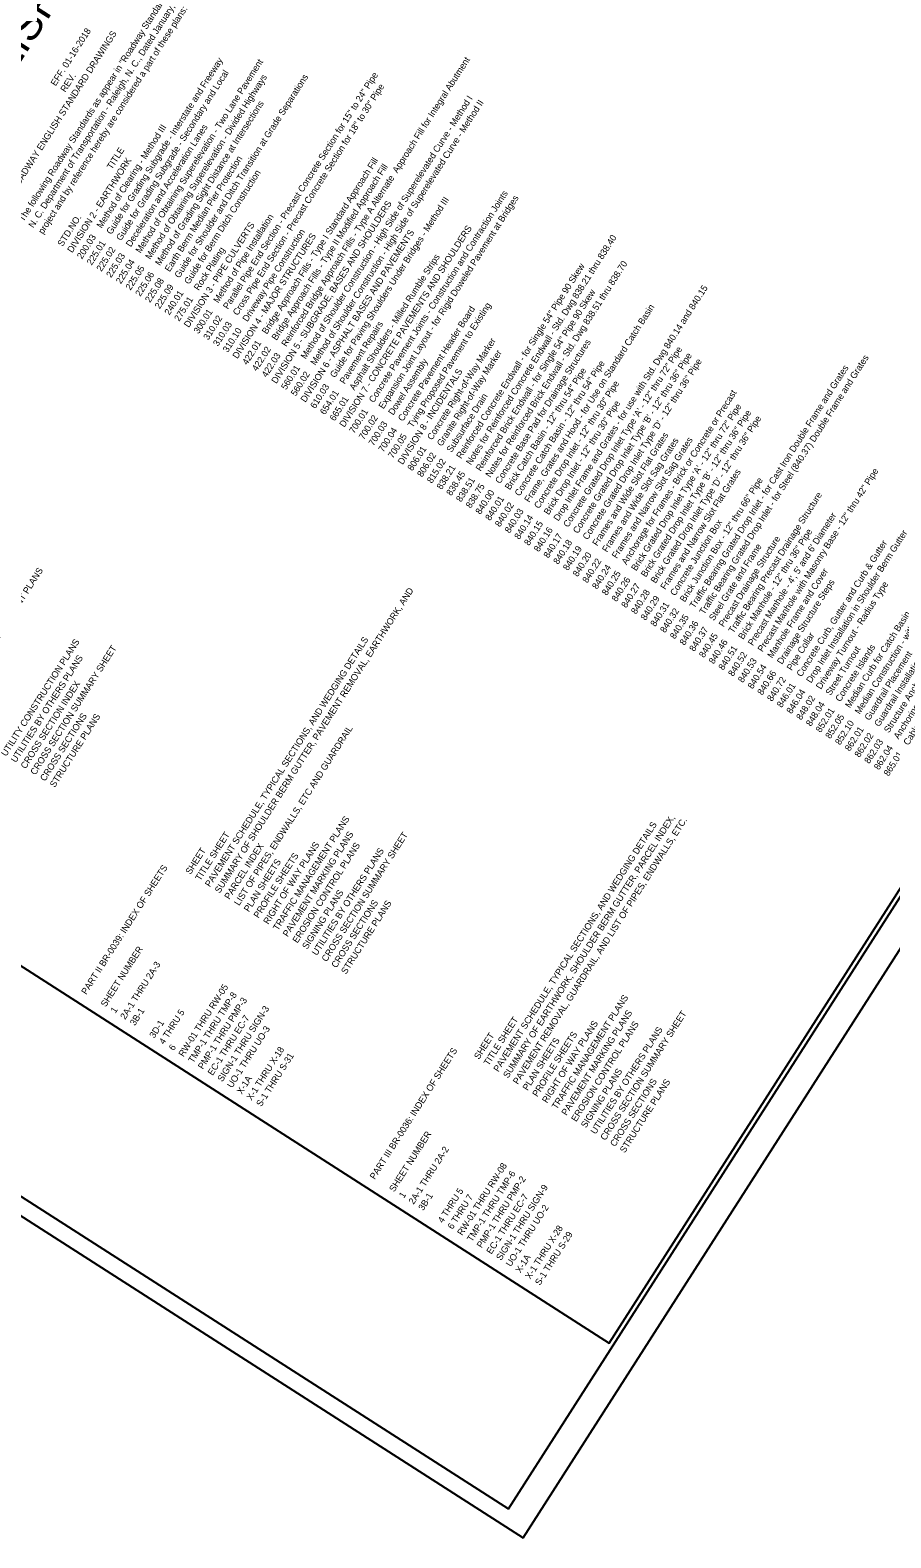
# Model space of a CAD drawing. Extents: x 2347249 to 2361994, y 830101 to 846299.
# Drawn here: x 2351497 to 2357017, y 830101 to 839761 of the extents above; entities that cross this region are included whole.
import ezdxf

# ---------------------------------------------------------------- set-up
doc = ezdxf.new("R2010")
doc.units = 0
for name, color, linetype in [('Sheet Data Field CELL', 7, 'Continuous'), ('Sheet Plot Border Inside CELL', 7, 'Continuous'), ('Sheet Plot Border Outside CELL', 7, 'Continuous'), ('Sheet Symbology CELL', 7, 'Continuous')]:
    doc.layers.add(name, color=color, linetype=linetype)

msp = doc.modelspace()

# ---------------------------------------------------------------- linework, layer by layer
at = {"layer": 'Sheet Plot Border Inside CELL'}
msp.add_lwpolyline([(2354564.1, 830285.9), (2361823.6, 841618.9), (2354715.9, 846171.7), (2347456.5, 834838.7)], close=True, dxfattribs=at)
at = {"layer": 'Sheet Plot Border Outside CELL'}
msp.add_lwpolyline([(2354658.7, 830100.6), (2361994.4, 841552.6), (2354584.3, 846299.2), (2347248.6, 834847.2)], close=True, dxfattribs=at)
at = {"layer": 'Sheet Symbology CELL'}
msp.add_lwpolyline([(2354678.6, 846075.7), (2348144.5, 835875), (2355211, 831348.5), (2361745.1, 841549.2)], close=True, dxfattribs=at)

# ---------------------------------------------------------------- texts
at = {"layer": 'Sheet Data Field CELL'}
for s, height, p in [('INDEX OF SHEETS, GENERAL NOTES AND 2018 ', 200, (2350018.7, 837720)), ('ROADWAY ENGLISH STANDARD DRAWINGS', 200, (2350290, 837764.1)), ('The following Roadway Standards as appear in "Roadway Standard Drawings" Highway Design Branch -', 42, (2351455.7, 838530.2)), ('N. C. Department of Transportation - Raleigh, N. C., Dated January, 2018 are applicable to this ', 42, (2351518, 838490.3)), ('project and by reference hereby are considered a part of these plans:', 42, (2351580.3, 838450.4)), ('                                                      EFF. 01-16-2018', 42, (2351206.4, 838689.9)), ('2018 ROADWAY ENGLISH STANDARD DRAWINGS', 42, (2351331.1, 838610)), ('225.01    Guide for Grading Subgrade - Interstate and Freeway', 42, (2351891.9, 838250.8)), ('225.04    Method of Obtaining Superelevation - Two Lane Pavement', 42, (2352078.9, 838131)), ('422.03    Reinforced Bridge Approach Fills - Type A Alternate  Approach Fill for Integral Abutment', 42, (2353013.7, 837532.2)), ('                                                      REV. ', 42, (2351268.7, 838650)), ('225.02    Guide for Grading Subgrade - Secondary and Local', 42, (2351954.3, 838210.8)), ('225.05    Method of Obtaining Superelevation - Divided Highways', 42, (2352141.2, 838091.1)), ('225.09    Guide for Shoulder and Ditch Transition at Grade Separations', 42, (2352328.2, 837971.3)), ('310.02    Parallel Pipe End Section - Precast Concrete Section for 15" to 24" Pipe', 42, (2352639.8, 837771.7)), ('310.03    Cross Pipe End Section - Precast Concrete Section for 18" to 30" Pipe', 42, (2352702.1, 837731.8)), ('225.06    Method of Grading Sight Distance at Intersections', 42, (2352203.5, 838051.2)), ('560.01    Method of Shoulder Construction - High Side of Superelevated Curve - Method I', 42, (2353138.3, 837452.4)), ('560.02    Method of Shoulder Construction - High Side of Superelevated Curve - Method II', 42, (2353200.7, 837412.5)), ('200.03    Method of Clearing - Method III', 42, (2351829.6, 838290.7)), ('225.03    Deceleration and Acceleration Lanes', 42, (2352016.6, 838170.9)), ('STD.NO.                       TITLE', 42, (2351705, 838370.5)), ('DIVISION 2 - EARTHWORK', 42, (2351767.3, 838330.6)), ('225.08    Earth Berm Median Pier Protection', 42, (2352265.9, 838011.3)), ('422.01    Bridge Approach Fills - Type I Standard Approach Fill', 42, (2352889.1, 837612.1)), ('422.02    Bridge Approach Fills - Type II Modified Approach Fill', 42, (2352951.4, 837572.1)), ('240.01    Guide for Berm Ditch Construction', 42, (2352390.5, 837931.4)), ('700.01    Concrete Pavement Joints - Construction and Contraction Joints ', 42, (2353574.6, 837172.9)), ('700.02    Expansion Joint Layout - for Rigid Doweled Pavement at Bridges', 42, (2353636.9, 837133)), ('DIVISION 5 - SUBGRADE, BASES AND SHOULDERS', 42, (2353076, 837492.3)), ('610.03    Guide for Paving Shoulders Under Bridges - Method III', 42, (2353325.3, 837332.6)), ('DIVISION 3 - PIPE CULVERTS', 42, (2352515.1, 837851.6)), ('300.01    Method of Pipe Installation ', 42, (2352577.5, 837811.7)), ('DIVISION 7 - CONCRETE PAVEMENTS AND SHOULDERS', 42, (2353512.3, 837212.9)), ('310.10    Driveway Pipe Construction', 42, (2352764.4, 837691.9)), ('DIVISION 4 - MAJOR STRUCTURES', 42, (2352826.7, 837652)), ('DIVISION 6 - ASPHALT BASES AND PAVEMENTS', 42, (2353263, 837372.5)), ('838.45    Notes for Reinforced Concrete Endwall - Std. Dwg 838.21 thru 838.40', 42, (2354197.8, 836773.7)), ('275.01    Rock Plating', 42, (2352452.8, 837891.5)), ('665.01    Asphalt Shoulders - Milled Rumble Strips', 42, (2353450, 837252.8)), ('838.21    Reinforced Concrete Endwall - for Single 54" Pipe 90 Skew', 42, (2354135.5, 836813.7)), ('838.75    Notes for Reinforced Brick Endwall - Std. Dwg 838.51 thru 838.70', 42, (2354322.4, 836693.9)), ('840.16    Drop Inlet Frame and Grates - for use with Std. Dwg 840.14 and 840.15', 42, (2354758.7, 836414.5)), ('838.51    Reinforced Brick Endwall - for Single 54" Pipe 90 Skew', 42, (2354260.1, 836733.8)), ('700.04    Concrete Pavement Header Board', 42, (2353761.6, 837053.2)), ('700.05    Tying Proposed Pavement to Existing', 42, (2353823.9, 837013.3)), ('840.03    Frame, Grates and Hood - for Use on Standard Catch Basin', 42, (2354571.7, 836534.2)), ('654.01    Pavement Repairs', 42, (2353387.6, 837292.7)), ('806.01    Concrete Right-of-Way Marker', 42, (2353948.5, 836933.4)), ('840.00    Concrete Base Pad for Drainage Structures', 42, (2354384.8, 836654)), ('840.17    Concrete Grated Drop Inlet Type \'A\' - 12" thru 72" Pipe', 42, (2354821, 836374.5)), ('700.03    Dowel Assembly', 42, (2353699.2, 837093.1)), ('806.02    Granite Right-of-Way Marker', 42, (2354010.8, 836893.5)), ('840.02    Concrete Catch Basin - 12" thru 54" Pipe', 42, (2354509.4, 836574.1)), ('840.18    Concrete Grated Drop Inlet Type \'B\' - 12" thru 36" Pipe', 42, (2354883.3, 836334.6)), ('840.19    Concrete Grated Drop Inlet Type \'D\' - 12" thru 36" Pipe', 42, (2354945.6, 836294.7)), ('840.36    Traffic Bearing Grated Drop Inlet - for Steel (840.37) Double Frame and Grates', 42, (2355693.5, 835815.7)), ('DIVISION 8 - INCIDENTALS', 42, (2353886.2, 836973.3)), ('840.01    Brick Catch Basin - 12" thru 54" Pipe', 42, (2354447.1, 836614.1)), ('840.35    Traffic Bearing Grated Drop Inlet - for Cast Iron Double Frame and Grates', 42, (2355631.2, 835855.6)), ('840.14    Concrete Drop Inlet - 12" thru 30" Pipe', 42, (2354634, 836494.3)), ('840.25    Anchorage for Frames - Brick or Concrete or Precast', 42, (2355194.9, 836135)), ('815.02    Subsurface Drain', 42, (2354073.2, 836853.6)), ('840.15    Brick Drop Inlet - 12" thru 30" Pipe', 42, (2354696.4, 836454.4)), ('840.26    Brick Grated Drop Inlet Type \'A\' - 12" thru 72" Pipe', 42, (2355257.2, 836095.1)), ('840.27    Brick Grated Drop Inlet Type \'B\' - 12" thru 36" Pipe', 42, (2355319.6, 836055.2)), ('840.28    Brick Grated Drop Inlet Type \'D\' - 12" thru 36" Pipe', 42, (2355381.9, 836015.3)), ('840.20    Frames and Wide Slot Flat Grates', 42, (2355008, 836254.8)), ('840.22    Frames and Wide Slot Sag Grates', 42, (2355070.3, 836214.9)), ('840.24    Frames and Narrow Slot Sag Grates', 42, (2355132.6, 836174.9)), ('840.29    Frames and Narrow Slot Flat Grates', 42, (2355444.2, 835975.3)), ('840.32    Brick Junction Box - 12" thru 66" Pipe', 42, (2355568.8, 835895.5)), ('840.53    Precast Manhole with Masonry Base - 12" thru 42" Pipe', 42, (2356067.4, 835576.1)), ('840.46    Traffic Bearing Precast Drainage Structure', 42, (2355880.4, 835695.9)), ('852.05    Median Curb for Catch Basin - for Use with 1\'-6" Curb and Gutter', 42, (2356628.3, 835216.9)), ("840.52    Precast Manhole - 4', 5' and 6' Diameter", 42, (2356005.1, 835616.1)), ('840.31    Concrete Junction Box', 42, (2355506.5, 835935.4)), ('840.45    Precast Drainage Structure', 42, (2355818.1, 835735.8)), ('840.51    Brick Manhole - 12" thru 36" Pipe', 42, (2355942.8, 835656)), ('846.01    Concrete Curb, Gutter and Curb & Gutter', 42, (2356316.7, 835416.5)), ('846.04    Drop Inlet Installation in Shoulder Berm Gutter', 42, (2356379, 835376.6)), ('840.37    Steel Grate and Frame', 42, (2355755.8, 835775.7)), ('862.04    Anchoring End of Guardrail - B-77 and B-83 Anchor Units', 42, (2356939.9, 835017.3)), ('TRANSPORTATION MANAGEMENT PLANS', 42, (2350969.8, 835343.8)), ('840.54    Manhole Frame and Cover', 42, (2356129.7, 835536.2)), ('852.10    Median Construction - with Curb and Gutter', 42, (2356690.6, 835177)), ('SUMMARY OF SHOULDER BERM GUTTER, PAVEMENT REMOVAL, EARTHWORK, AND ', 42, (2352712.8, 834227.3)), ('840.66    Drainage Structure Steps', 42, (2356192, 835496.3)), ('848.02    Driveway Turnout - Radius Type', 42, (2356441.3, 835336.6)), ('840.72    Pipe Collar', 42, (2356254.4, 835456.4)), ('UTILITY CONSTRUCTION PLANS', 42, (2351343.7, 835104.3)), ('CROSS SECTION SUMMARY SHEET', 42, (2351530.7, 834984.5)), ('PAVEMENT SCHEDULE, TYPICAL SECTIONS, AND WEDGING DETAILS', 42, (2352650.5, 834267.2)), ('848.04    Street Turnout', 42, (2356503.6, 835296.7)), ('852.01    Concrete Islands', 42, (2356566, 835256.8)), ('UTILITIES BY OTHERS PLANS', 42, (2351406.1, 835064.4)), ('862.01    Guardrail Placement', 42, (2356752.9, 835137)), ('862.02    Guardrail Installation', 42, (2356815.2, 835097.1)), ('862.03    Structure Anchor Units', 42, (2356877.6, 835057.2)), ('CROSS SECTION INDEX', 42, (2351468.4, 835024.4)), ('865.01    Cable Guiderail', 42, (2357002.2, 834977.4)), ('CROSS SECTIONS', 42, (2351593, 834944.6)), ('STRUCTURE PLANS ', 42, (2351655.4, 834904.7)), ('LIST OF PIPES, ENDWALLS, ETC AND GUARDRAIL', 42, (2352837.5, 834147.5)), ('TRAFFIC MANAGEMENT PLANS', 42, (2353086.7, 833987.8)), ('PAVEMENT SCHEDULE, TYPICAL SECTIONS, AND WEDGING DETAILS', 42, (2354500.1, 833082.4)), ('SUMMARY OF EARTHWORK, SHOULDER BERM GUTTER, PARCEL INDEX, ', 42, (2354562.4, 833042.5)), ('PAVEMENT REMOVAL, GUARDRAIL, AND LIST OF PIPES, ENDWALLS, ETC.', 42, (2354624.8, 833002.6)), ('TITLE SHEET', 42, (2352588.2, 834307.1)), ('PARCEL INDEX', 42, (2352775.1, 834187.4)), ('RIGHT OF WAY PLANS', 42, (2353024.4, 834027.7)), ('PAVEMENT MARKING PLANS', 42, (2353149.1, 833947.9)), ('EROSION CONTROL PLANS', 42, (2353211.4, 833907.9)), ('CROSS SECTION SUMMARY SHEET', 42, (2353398.3, 833788.2)), ('SHEET', 42, (2352525.9, 834347.1)), ('PLAN SHEETS', 42, (2352899.8, 834107.5)), ('PROFILE SHEETS', 42, (2352962.1, 834067.6)), ('UTILITIES BY OTHERS PLANS', 42, (2353336, 833828.1)), ('PART II BR-0039: INDEX OF SHEETS', 42, (2351857.5, 833578.1)), ('SIGNING PLANS', 42, (2353273.7, 833868)), ('CROSS SECTIONS', 42, (2353460.7, 833748.3)), ('STRUCTURE PLANS ', 42, (2353523, 833708.4)), ('SHEET NUMBER', 42, (2351982.2, 833498.3)), ('2A-1 THRU 2A-3', 42, (2352106.8, 833418.4)), ('RW-01 THRU RW-05', 42, (2352480.7, 833178.9)), ('TMP-1 THRU TMP-8', 42, (2352543, 833139)), ('TRAFFIC MANAGEMENT PLANS', 42, (2354874, 832842.9)), ('1', 42, (2352044.5, 833458.4)), ('3B-1', 42, (2352169.1, 833378.5)), ('4 THRU 5', 42, (2352356.1, 833258.8)), ('PMP-1 THRU PMP-3', 42, (2352605.4, 833099.1)), ('SIGN-1 THRU SIGN-3', 42, (2352730, 833019.2)), ('PAVEMENT MARKING PLANS', 42, (2354936.4, 832803)), ('CROSS SECTION SUMMARY SHEET', 42, (2355185.6, 832643.3)), ('3D-1', 42, (2352293.8, 833298.7)), ('EC-1 THRU EC-7', 42, (2352667.7, 833059.2)), ('TITLE SHEET', 42, (2354437.8, 833122.4)), ('RIGHT OF WAY PLANS', 42, (2354811.7, 832882.8)), ('EROSION CONTROL PLANS', 42, (2354998.7, 832763.1)), ('UO-1 THRU UO-3', 42, (2352792.3, 832979.3)), ('SHEET', 42, (2354375.5, 833162.3)), ('PLAN SHEETS', 42, (2354687.1, 832962.7)), ('PROFILE SHEETS', 42, (2354749.4, 832922.8)), ('UTILITIES BY OTHERS PLANS', 42, (2355123.3, 832683.2)), ('6', 42, (2352418.4, 833218.8)), ('X-1 THRU X-18', 42, (2352917, 832899.5)), ('S-1 THRU S-31', 42, (2352979.3, 832859.6)), ('PART III BR-0036: INDEX OF SHEETS', 42, (2353707.1, 832393.3)), ('SIGNING PLANS', 42, (2355061, 832723.2)), ('X-1A', 42, (2352854.6, 832939.4)), ('CROSS SECTIONS', 42, (2355248, 832603.4)), ('STRUCTURE PLANS ', 42, (2355310.3, 832563.5)), ('SHEET NUMBER', 42, (2353831.8, 832313.5)), ('2A-1 THRU 2A-2', 42, (2353956.4, 832233.7)), ('RW-01 THRU RW-08', 42, (2354268, 832034.1)), ('TMP-1 THRU TMP-6', 42, (2354330.3, 831994.1)), ('PMP-1 THRU PMP-2', 42, (2354392.7, 831954.2)), ('4 THRU 5', 42, (2354143.4, 832113.9)), ('SIGN-1 THRU SIGN-9', 42, (2354517.3, 831874.4)), ('1', 42, (2353894.1, 832273.6)), ('3B-1', 42, (2354018.7, 832193.7)), ('6 THRU 7', 42, (2354205.7, 832074)), ('EC-1 THRU EC-7', 42, (2354455, 831914.3)), ('UO-1 THRU UO-2', 42, (2354579.6, 831834.5)), ('X-1 THRU X-28', 42, (2354704.3, 831754.6)), ('S-1 THRU S-29', 42, (2354766.6, 831714.7)), ('X-1A', 42, (2354641.9, 831794.5))]:
    msp.add_text(s, height=height, rotation=57.35811, dxfattribs=at).set_placement(p)
at = {"layer": 'Sheet Symbology CELL'}
msp.add_text('STATE OF NORTH CAROLINA, DIVISION OF HIGHWAYS', height=171.352, rotation=57.35811, dxfattribs=at).set_placement((2350295.6, 838818.4))

doc.saveas('drawing.dxf')
